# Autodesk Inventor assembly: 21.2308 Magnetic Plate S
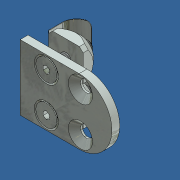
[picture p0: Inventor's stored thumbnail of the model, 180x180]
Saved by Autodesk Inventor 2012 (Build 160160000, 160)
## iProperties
Created: 2014-05
Part Number: 21.2308 Magnetic Plate S
Document SubType Name: Assembly
Designer: Admin
Author: Admin
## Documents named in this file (4)
- C:\Andys Backup Data\ANDY'S INVENTOR\INVENTOR LIBRARIES\PARTS LIBRARY\HANDLES LOCKS STOPS\21.2308 Magnetic Plate S.iam
- C:\Andys Backup Data\ANDY'S INVENTOR\INVENTOR LIBRARIES\PARTS LIBRARY\HANDLES LOCKS STOPS\SUBCOMPONENTS\21.2308_Magnetic_Plate_S.ipt
- C:\Andys Backup Data\ANDY'S INVENTOR\INVENTOR LIBRARIES\PARTS LIBRARY\FASTENING ELEMENTS\SCREWS COUNTERSUNK\21.1501 M4X16 CSUNK.IPT
- C:\Andys Backup Data\ANDY'S INVENTOR\INVENTOR LIBRARIES\PARTS LIBRARY\FASTENING ELEMENTS\NUTS\21.1310_2 M4 SQUARE NUT POS FXG.ipt
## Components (5 placed, 3 different names)
1. 21.2308_Magnetic_Plate_S:1 — Insert:1, Insert:2, Insert:3, Insert:4, Angle:1, Angle:2
2. 21.1501 M4x16 C'SUNK:1 — Insert:2
3. 21.1501 M4x16 C'SUNK:2 — Insert:1
4. 21.1310_2 M4 SQUARE NUT POS FXG:1 — Insert:3, Angle:1
5. 21.1310_2 M4 SQUARE NUT POS FXG:2 — Insert:4, Angle:2
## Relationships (6: Insert 4, Angle 2)
- Insert:1: 21.2308_Magnetic_Plate_S:1 ↔ 21.1501 M4x16 C'SUNK:2
- Insert:2: 21.2308_Magnetic_Plate_S:1 ↔ 21.1501 M4x16 C'SUNK:1
- Insert:3: 21.2308_Magnetic_Plate_S:1 ↔ 21.1310_2 M4 SQUARE NUT POS FXG:1
- Insert:4: 21.2308_Magnetic_Plate_S:1 ↔ 21.1310_2 M4 SQUARE NUT POS FXG:2
- Angle:1: 21.2308_Magnetic_Plate_S:1 ↔ 21.1310_2 M4 SQUARE NUT POS FXG:1
- Angle:2: 21.2308_Magnetic_Plate_S:1 ↔ 21.1310_2 M4 SQUARE NUT POS FXG:2
